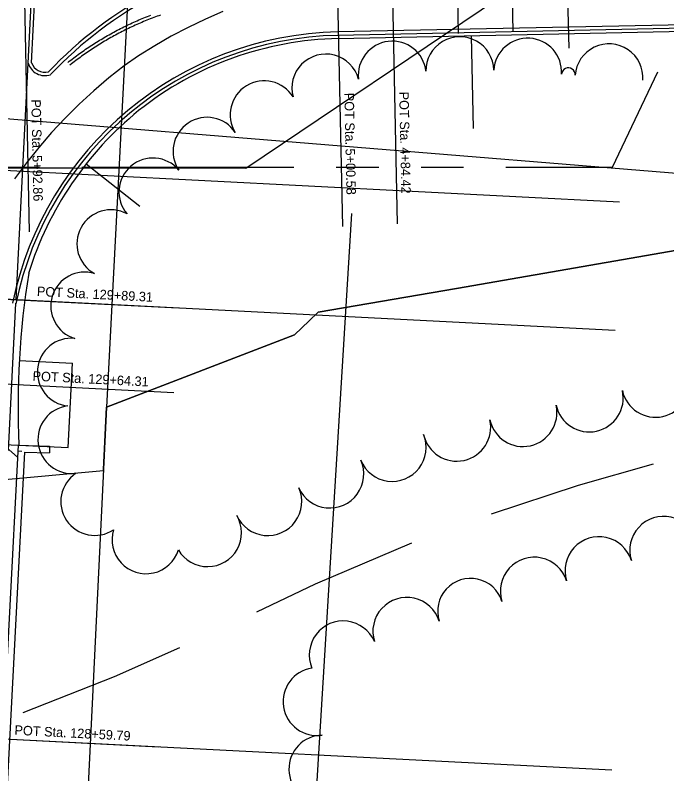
# Model space of a CAD drawing. Extents: x -25029 to 2274964, y -81170 to 687028.
# Drawn here: x -3987.6 to -3795.5, y -66880.9 to -66657.3 of the extents above; entities that cross this region are included whole.
import ezdxf

# ---------------------------------------------------------------- set-up
doc = ezdxf.new("R2010")
doc.units = 0
for name, color, linetype in [('81911BEA - RW_X_Fee_RW', 7, 'Continuous'), ('AP_X_Runway', 7, 'Continuous'), ('BD_X_Canopy', 7, 'Continuous'), ('BR_X_Rail_Object', 7, 'Continuous'), ('Default', 7, 'Continuous'), ('DIVISIONS', 7, 'Continuous'), ('DRIVWY', 7, 'Continuous'), ('DV_X_Corp_Line', 7, 'Continuous'), ('GE_X_CL_100', 7, 'Continuous'), ('GE_X_CL_20', 7, 'Continuous'), ('PM_P_CL_Double_Solid', 7, 'Continuous'), ('PV_X_Curb', 7, 'Continuous'), ('PV_X_EOP', 7, 'Continuous'), ('RD_P_Gate', 7, 'Continuous'), ('RD_X_GR_Rt', 7, 'Continuous'), ('SC_Scratch5', 7, 'Continuous'), ('TREES', 7, 'Continuous')]:
    doc.layers.add(name, color=color, linetype=linetype)

msp = doc.modelspace()

# ---------------------------------------------------------------- linework, layer by layer
at = {"layer": '81911BEA - RW_X_Fee_RW'}
for p, q in [((-3944.88, -66468.51), (-3960.69, -66772.81)), ((-3960.69, -66772.81), (-3964.79, -66858.23)), ((-3964.79, -66858.23), (-3968.48, -66935))]:
    msp.add_line(p, q, dxfattribs=at)
at = {"layer": 'AP_X_Runway'}
for p, q in [((-4009.34, -66702.04), (-3809.48, -66712.25)), ((-3985.82, -66702.25), (-3970.47, -66702.29)), ((-4011.27, -66739.88), (-3810.76, -66750.13)), ((-4017.88, -66869.24), (-3811.75, -66879.76))]:
    msp.add_line(p, q, dxfattribs=at)
at = {"layer": 'BD_X_Canopy'}
msp.add_line((-3908.26, -67042.25), (-3888.37, -66715.74), dxfattribs=at)
at = {"layer": 'BR_X_Rail_Object'}
for p, q in [((-4037.8, -66742.47), (-3986.92, -66787.57)), ((-3986.73, -66784.01), (-3997.37, -66988.52)), ((-3986.73, -66784.01), (-3977.44, -66784.3)), ((-3984.84, -66786.07), (-3995.05, -66982.32)), ((-3984.84, -66786.07), (-3977.51, -66786.3)), ((-3977.44, -66784.3), (-3977.51, -66786.3))]:
    msp.add_line(p, q, dxfattribs=at)
at = {"layer": 'Default'}
for p, q in [((-4008.53, -66686.26), (-3651.55, -66715.33)), ((-3986.58, -66785.7), (-3985.58, -66785.75))]:
    msp.add_line(p, q, dxfattribs=at)
at = {"layer": 'DIVISIONS'}
for p, q in [((-3992.94, -66702.04), (-3980.44, -66702.04)), ((-3967.94, -66702.04), (-3905.44, -66702.04)), ((-3892.94, -66702.04), (-3880.44, -66702.04)), ((-3867.94, -66702.04), (-3855.44, -66702.04)), ((-3857.49, -66737.79), (-3752.46, -66719.61)), ((-3857.49, -66737.79), (-3752.46, -66719.61)), ((-3752.46, -66719.61), (-3857.49, -66737.79)), ((-3752.46, -66719.61), (-3857.49, -66737.79)), ((-3898.28, -66744.85), (-3857.49, -66737.79)), ((-3898.28, -66744.85), (-3857.49, -66737.79)), ((-3857.49, -66737.79), (-3898.28, -66744.85)), ((-3857.49, -66737.79), (-3898.28, -66744.85)), ((-3900.9, -66747.34), (-3898.28, -66744.85)), ((-3900.9, -66747.34), (-3898.28, -66744.85)), ((-3898.28, -66744.85), (-3900.9, -66747.34)), ((-3898.28, -66744.85), (-3900.9, -66747.34)), ((-3905.26, -66751.47), (-3900.9, -66747.34)), ((-3905.26, -66751.47), (-3900.9, -66747.34)), ((-3900.9, -66747.34), (-3905.26, -66751.47)), ((-3900.9, -66747.34), (-3905.26, -66751.47)), ((-3960.69, -66772.81), (-3905.26, -66751.47)), ((-3960.69, -66772.81), (-3905.26, -66751.47)), ((-3905.26, -66751.47), (-3960.69, -66772.81)), ((-3905.26, -66751.47), (-3960.69, -66772.81)), ((-3961.57, -66791.16), (-3960.69, -66772.81)), ((-4000.13, -66794.95), (-3961.59, -66791.43))]:
    msp.add_line(p, q, dxfattribs=at)
msp.add_lwpolyline([(-3842.94, -66702.04), (-3811.53, -66702.04), (-3798.21, -66673.94)], dxfattribs=at)
at = {"layer": 'DRIVWY'}
for points in [[(-3847.21, -66804.26), (-3821.55, -66795.85), (-3799.43, -66789.54)], [(-3916.36, -66833.1), (-3899.04, -66824.88), (-3870.66, -66812.84)], [(-3985.21, -66862.78), (-3958.27, -66852.24), (-3939.04, -66843.63)]]:
    msp.add_lwpolyline(points, dxfattribs=at)
at = {"layer": 'DV_X_Corp_Line'}
for p, q in [((-3919.61, -66702.4), (-3840.6, -66649.11)), ((-4082.76, -66702.04), (-3919.61, -66702.4)), ((-3961.59, -66791.43), (-3961.57, -66791.16)), ((-3961.59, -66791.43), (-3961.57, -66791.16)), ((-3961.57, -66791.16), (-3961.59, -66791.43)), ((-3961.57, -66791.16), (-3961.59, -66791.43))]:
    msp.add_line(p, q, dxfattribs=at)
at = {"layer": 'GE_X_CL_100'}
msp.add_lwpolyline([(-3926.36, -66656.22), (-3931.53, -66658.43), (-3936.61, -66660.84), (-3941.59, -66663.45), (-3946.46, -66666.26), (-3951.22, -66669.25), (-3955.43, -66672.14), (-3960, -66675.75), (-3964.43, -66679.54), (-3968.72, -66683.49), (-3972.85, -66687.6), (-3976.83, -66691.86), (-3980.64, -66696.26), (-3984.29, -66700.81), (-3987.77, -66705.49)], dxfattribs=at)
at = {"layer": 'GE_X_CL_20'}
for p, q in [((-3892.59, -66651.2), (-3891.15, -66719.54)), ((-3876.43, -66650.86), (-3875.01, -66718.81)), ((-3984.85, -66653.13), (-3983.42, -66721.08)), ((-4010.27, -66739.94), (-3939.56, -66743.55)), ((-4011.55, -66764.9), (-3940.82, -66768.52)), ((-4016.88, -66869.29), (-3945.35, -66872.94))]:
    msp.add_line(p, q, dxfattribs=at)
at = {"layer": 'PM_P_CL_Double_Solid'}
for points in [[(-3972.05, -66671.19), (-3971.63, -66670.85), (-3971.2, -66670.52), (-3970.77, -66670.19), (-3970.34, -66669.86), (-3969.9, -66669.53), (-3969.47, -66669.21), (-3969.03, -66668.89), (-3968.59, -66668.57), (-3968.15, -66668.25), (-3967.7, -66667.94), (-3967.26, -66667.63), (-3966.81, -66667.32), (-3966.36, -66667.01), (-3965.91, -66666.71), (-3965.46, -66666.41), (-3965.01, -66666.11), (-3964.55, -66665.81), (-3964.09, -66665.52), (-3963.63, -66665.23), (-3963.17, -66664.94), (-3962.71, -66664.66), (-3962.24, -66664.38), (-3961.78, -66664.1), (-3961.31, -66663.82), (-3960.84, -66663.55), (-3960.37, -66663.28), (-3959.9, -66663.01), (-3959.42, -66662.74), (-3958.95, -66662.48), (-3958.47, -66662.22), (-3957.99, -66661.96), (-3957.51, -66661.71), (-3957.03, -66661.46), (-3956.55, -66661.21), (-3956.06, -66660.96), (-3955.58, -66660.72), (-3955.09, -66660.48), (-3954.6, -66660.24), (-3954.11, -66660.01), (-3953.62, -66659.78), (-3953.13, -66659.55), (-3952.63, -66659.32), (-3952.14, -66659.1), (-3951.64, -66658.88), (-3951.14, -66658.66), (-3950.64, -66658.45), (-3950.14, -66658.24), (-3949.64, -66658.03), (-3949.14, -66657.82), (-3948.63, -66657.62), (-3948.13, -66657.42), (-3947.62, -66657.23)], [(-3944.74, -66657.23), (-3945.25, -66657.41), (-3945.75, -66657.59), (-3946.26, -66657.78), (-3946.76, -66657.97), (-3947.26, -66658.16), (-3947.76, -66658.35), (-3948.26, -66658.55), (-3948.76, -66658.75), (-3949.26, -66658.95), (-3949.76, -66659.16), (-3950.25, -66659.37), (-3950.75, -66659.58), (-3951.24, -66659.8), (-3951.73, -66660.01), (-3952.22, -66660.23), (-3952.71, -66660.46), (-3953.2, -66660.68), (-3953.68, -66660.91), (-3954.17, -66661.14), (-3954.65, -66661.38), (-3955.13, -66661.62), (-3955.61, -66661.86), (-3956.09, -66662.1), (-3956.57, -66662.35), (-3957.05, -66662.6), (-3957.52, -66662.85), (-3958, -66663.1), (-3958.47, -66663.36), (-3958.94, -66663.62), (-3959.41, -66663.88), (-3959.87, -66664.15), (-3960.34, -66664.41), (-3960.8, -66664.68), (-3961.27, -66664.96), (-3961.73, -66665.23), (-3962.19, -66665.51), (-3962.65, -66665.79), (-3963.1, -66666.08), (-3963.56, -66666.37), (-3964.01, -66666.66), (-3964.46, -66666.95), (-3964.91, -66667.24), (-3965.36, -66667.54), (-3965.8, -66667.84), (-3966.25, -66668.14), (-3966.69, -66668.45), (-3967.13, -66668.76), (-3967.57, -66669.07), (-3968.01, -66669.38), (-3968.44, -66669.69), (-3968.87, -66670.01), (-3969.3, -66670.33), (-3969.73, -66670.66), (-3970.16, -66670.98), (-3970.59, -66671.31), (-3971.01, -66671.64), (-3971.43, -66671.97)]]:
    msp.add_lwpolyline(points, dxfattribs=at)
at = {"layer": 'PV_X_Curb'}
for p, q in [((-3982.73, -66671.27), (-3979.94, -66616.65)), ((-3689.73, -66658.95), (-3892.46, -66663.2)), ((-3989.57, -66785.55), (-3987.36, -66742.17))]:
    msp.add_line(p, q, dxfattribs=at)
for centre, radius, start, end in [((-3887.49, -66760.38), 125, 118.1708, 136.2332), ((-3890.39, -66762.18), 99, 91.2017, 168.4297), ((-3978.86, -66669.99), 4.08, 198.2598, 285.7006)]:
    msp.add_arc(centre, radius, start, end, dxfattribs=at)
at = {"layer": 'PV_X_EOP'}
for p, q in [((-3983.74, -66671.39), (-3980.92, -66616.06)), ((-3689.75, -66657.95), (-3892.48, -66662.2)), ((-3987.3, -66741.11), (-3983.74, -66671.39))]:
    msp.add_line(p, q, dxfattribs=at)
for centre, radius, start, end in [((-3887.49, -66760.38), 124, 118.1708, 136.3517), ((-3890.39, -66762.18), 100, 91.2017, 168.4297), ((-3978.86, -66669.99), 5.08, 196.0384, 288.9432)]:
    msp.add_arc(centre, radius, start, end, dxfattribs=at)
at = {"layer": 'RD_P_Gate'}
for p, q in [((-3853.17, -66663.31), (-3853.17, -66663.31)), ((-3853.17, -66663.31), (-3852.58, -66690.65)), ((-3840.67, -66663.04), (-3840.67, -66663.04)), ((-3828.17, -66662.77), (-3828.17, -66662.77)), ((-3815.68, -66662.5), (-3815.68, -66662.5)), ((-3803.18, -66662.23), (-3803.18, -66662.23)), ((-3903.12, -66664.97), (-3903.12, -66664.97)), ((-3890.66, -66664.13), (-3890.66, -66664.13)), ((-3878.16, -66663.85), (-3878.16, -66663.85)), ((-3865.67, -66663.58), (-3865.67, -66663.58)), ((-3915.38, -66667.39), (-3915.38, -66667.39)), ((-3927.23, -66671.35), (-3927.23, -66671.35)), ((-3938.47, -66676.79), (-3938.47, -66676.79)), ((-3948.92, -66683.63), (-3948.92, -66683.63)), ((-3958.36, -66691.8), (-3958.36, -66691.8)), ((-3966.69, -66701.11), (-3966.69, -66701.11)), ((-3966.69, -66701.11), (-3950.85, -66713.58)), ((-3973.78, -66711.39), (-3973.78, -66711.39)), ((-3979.54, -66722.48), (-3979.54, -66722.48)), ((-3983.74, -66734.15), (-3983.74, -66734.15)), ((-3985.36, -66746.55), (-3985.36, -66746.55)), ((-3986.36, -66759.01), (-3986.36, -66759.01)), ((-3986.36, -66759.01), (-3970.73, -66759.87)), ((-3972, -66784.74), (-3970.73, -66759.87)), ((-4013.46, -66782.64), (-3986.73, -66784.01)), ((-3986.48, -66784), (-3972, -66784.74))]:
    msp.add_line(p, q, dxfattribs=at)
at = {"layer": 'RD_X_GR_Rt'}
msp.add_line((-3892.35, -66664.16), (-3689.41, -66659.76), dxfattribs=at)
for centre, radius, start, end in [((-3890.43, -66761.68), 97.54, 91.1256, 128.5359), ((-3888.19, -66762.9), 99.9, 129.1071, 162.8032), ((-3735.94, -66772.78), 250.79, 170.9493, 182.5625)]:
    msp.add_arc(centre, radius, start, end, dxfattribs=at)
at = {"layer": 'SC_Scratch5'}
for p, q in [((-3840.81, -66662.12), (-3841.44, -66632.12)), ((-3825.17, -66632.78), (-3824.45, -66666.96)), ((-3857.33, -66649.46), (-3857.05, -66662.69))]:
    msp.add_line(p, q, dxfattribs=at)
at = {"layer": 'TREES'}
for centre, radius, start, end in [((-3876.46, -66674.92), 10, 6.6256, 186.6256), ((-3856.53, -66673.61), 10, 0.9404, 180.9404), ((-3836.55, -66674.04), 10, 356.5428, 176.5428), ((-3812.58, -66675.69), 10, 355.7219, 175.7219), ((-3896.04, -66678.72), 10, 15.3514, 195.3514), ((-3824.56, -66674.8), 2.01, 355.7219, 175.7219), ((-3914.2, -66686.6), 10, 31.5434, 211.5434), ((-3931.05, -66697.37), 10, 33.5918, 213.5918), ((-3947, -66709.38), 10, 40.3782, 220.3782), ((-3959.39, -66724.64), 10, 61.4913, 241.4913), ((-3967.09, -66742.99), 10, 72.9659, 252.9659), ((-3971.05, -66762.5), 10, 84.1066, 264.1066), ((-3798.87, -66765.78), 10, 192.4785, 12.4785), ((-3818.39, -66770.1), 10, 192.4785, 12.4785), ((-3970.88, -66782.38), 10, 96.8664, 276.8664), ((-3837.92, -66774.42), 10, 192.4785, 12.4785), ((-3857.45, -66778.74), 10, 192.4785, 12.4785), ((-3876.47, -66784.68), 10, 202.2103, 22.2103), ((-3894.86, -66792.53), 10, 203.9975, 23.9975), ((-3964.13, -66800.62), 10, 123.7358, 303.7358), ((-3913.13, -66800.66), 10, 203.9975, 23.9975), ((-3930.88, -66809.82), 10, 210.5727, 30.5727), ((-3796.46, -66814.99), 10, 17.5312, 197.5312), ((-3949.03, -66811.92), 10, 162.6417, 342.6417), ((-3815.53, -66821.01), 10, 17.5312, 197.5312), ((-3834.6, -66827.04), 10, 17.5312, 197.5312), ((-3853.38, -66832.97), 9.7, 17.5312, 197.5312), ((-3872.17, -66838.9), 10, 17.5312, 197.5312), ((-3890.91, -66845.82), 10, 22.96, 202.96), ((-3898.62, -66859.6), 10, 98.6553, 278.6553), ((-3896.91, -66879.49), 10, 91.1811, 271.1811)]:
    msp.add_arc(centre, radius, start, end, dxfattribs=at)

# ---------------------------------------------------------------- texts
at = {"layer": 'GE_X_CL_20'}
for s, rotation, p in [('POT Sta. 5+00.58', 271.2018, (-3890.58, -66680.16)), ('POT Sta. 4+84.42', 271.2018, (-3874.42, -66679.82)), ('POT Sta. 5+92.86', 271.2018, (-3982.84, -66682.1)), ('POT Sta. 129+89.31', 357.076, (-3981.24, -66740.02)), ('POT Sta. 129+64.31', 357.076, (-3982.51, -66764.98)), ('POT Sta. 128+59.79', 357.076, (-3987.85, -66869.37))]:
    msp.add_text(s, height=2.8, rotation=rotation, dxfattribs=at).set_placement(p)

doc.saveas('drawing.dxf')
